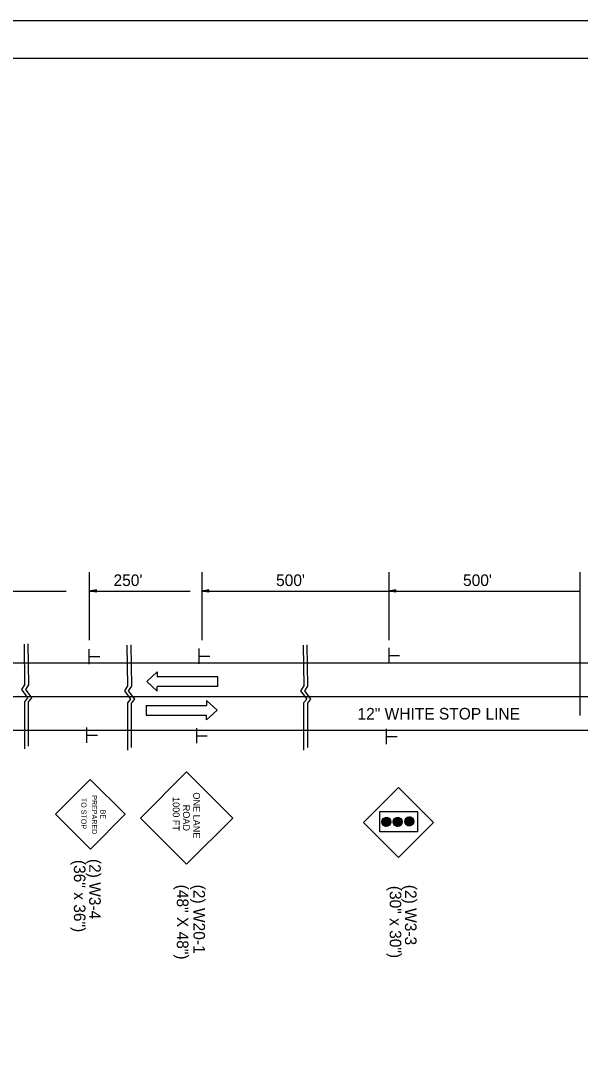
# Model space of a CAD drawing. Extents: x 1398460 to 1408037, y 380768 to 383968.
# Drawn here: x 1399523 to 1399812, y 382368 to 382901 of the extents above; entities that cross this region are included whole.
import ezdxf

# ---------------------------------------------------------------- set-up
doc = ezdxf.new("R2010")
doc.units = 0
for name, color, linetype in [('Default', 7, 'Continuous'), ('R_Border', 7, 'Continuous'), ('R_MOT', 7, 'Continuous'), ('R_No Plot', 7, 'Continuous')]:
    doc.layers.add(name, color=color, linetype=linetype)

msp = doc.modelspace()

# ---------------------------------------------------------------- linework, layer by layer
at = {"layer": 'Default'}
for p, q in [((1399558.31, 382615.8), (1399558.31, 382580.59)), ((1399616.41, 382615.8), (1399616.41, 382580.59)), ((1399713.06, 382615.8), (1399713.06, 382580.59)), ((1399811.91, 382615.8), (1399811.91, 382541.66)), ((1399494.15, 382606.01), (1399546.34, 382606.01)), ((1399562.06, 382606.57), (1399558.31, 382606.01)), ((1399558.31, 382606.01), (1399610.5, 382606.01)), ((1399562.06, 382605.45), (1399558.31, 382606.01)), ((1399562.06, 382606.48), (1399558.93, 382606.01)), ((1399562.06, 382605.54), (1399558.93, 382606.01)), ((1399562.06, 382606.39), (1399559.58, 382606.01)), ((1399562.06, 382605.64), (1399559.58, 382606.01)), ((1399562.06, 382606.29), (1399560.2, 382606.01)), ((1399562.06, 382605.73), (1399560.2, 382606.01)), ((1399562.06, 382606.2), (1399560.84, 382606.01)), ((1399562.06, 382605.83), (1399560.84, 382606.01)), ((1399562.06, 382606.1), (1399561.47, 382606.01)), ((1399562.06, 382605.92), (1399561.47, 382606.01)), ((1399562.06, 382605.45), (1399562.06, 382606.57)), ((1399620.16, 382606.57), (1399616.41, 382606.01)), ((1399616.41, 382606.01), (1399713.9, 382606.01)), ((1399620.16, 382605.45), (1399616.41, 382606.01)), ((1399620.16, 382606.48), (1399617.04, 382606.01)), ((1399620.16, 382605.54), (1399617.04, 382606.01)), ((1399620.16, 382606.39), (1399617.68, 382606.01)), ((1399620.16, 382605.64), (1399617.68, 382606.01)), ((1399620.16, 382606.29), (1399618.31, 382606.01)), ((1399620.16, 382605.73), (1399618.31, 382606.01)), ((1399620.16, 382606.2), (1399618.94, 382606.01)), ((1399620.16, 382605.83), (1399618.94, 382606.01)), ((1399620.16, 382606.1), (1399619.57, 382606.01)), ((1399620.16, 382605.92), (1399619.57, 382606.01)), ((1399620.16, 382605.45), (1399620.16, 382606.57)), ((1399716.81, 382606.57), (1399713.06, 382606.01)), ((1399713.06, 382606.01), (1399811.9, 382606.01)), ((1399716.81, 382605.45), (1399713.06, 382606.01)), ((1399716.81, 382606.48), (1399713.69, 382606.01)), ((1399716.81, 382605.54), (1399713.69, 382606.01)), ((1399716.81, 382606.39), (1399714.33, 382606.01)), ((1399716.81, 382605.64), (1399714.33, 382606.01)), ((1399716.81, 382606.29), (1399714.96, 382606.01)), ((1399716.81, 382605.73), (1399714.96, 382606.01)), ((1399716.81, 382606.2), (1399715.59, 382606.01)), ((1399716.81, 382605.83), (1399715.59, 382606.01)), ((1399716.81, 382606.1), (1399716.22, 382606.01)), ((1399716.81, 382605.92), (1399716.22, 382606.01)), ((1399716.81, 382605.45), (1399716.81, 382606.57)), ((1399558.31, 382568.22), (1399558.31, 382576.05)), ((1399615.11, 382568.43), (1399615.11, 382576.26)), ((1399713.25, 382568.85), (1399713.25, 382576.68)), ((1399518.14, 382568.89), (1399578.99, 382568.89)), ((1399558.42, 382572.11), (1399563.76, 382572.11)), ((1399578.99, 382568.89), (1399665.59, 382568.89)), ((1399615.23, 382572.32), (1399620.57, 382572.32)), ((1399665.59, 382568.89), (1399825.51, 382568.89)), ((1399713.36, 382572.75), (1399718.71, 382572.75)), ((1399517.8, 382551.51), (1399578.99, 382551.51)), ((1399578.99, 382551.51), (1399665.59, 382551.51)), ((1399665.59, 382551.51), (1399825.51, 382551.51)), ((1399517.46, 382534.12), (1399591.81, 382534.12)), ((1399557.04, 382527.58), (1399557.04, 382535.4)), ((1399557.16, 382531.47), (1399562.5, 382531.47)), ((1399578.99, 382534.12), (1399674.76, 382534.12)), ((1399613.85, 382527.37), (1399613.85, 382535.19)), ((1399613.96, 382531.26), (1399619.3, 382531.26)), ((1399665.59, 382534.12), (1399825.51, 382534.12)), ((1399711.99, 382526.94), (1399711.99, 382534.77)), ((1399712.1, 382530.84), (1399717.44, 382530.84)), ((1399584.72, 382488.66), (1399608.6, 382512.57)), ((1399632.51, 382488.66), (1399608.6, 382512.57)), ((1399540.77, 382490.6), (1399558.78, 382508.68)), ((1399576.84, 382490.66), (1399558.78, 382508.68)), ((1399700.12, 382486.35), (1399718.13, 382504.42)), ((1399736.19, 382486.41), (1399718.13, 382504.42)), ((1399558.85, 382472.59), (1399540.77, 382490.6)), ((1399558.85, 382472.59), (1399576.84, 382490.66)), ((1399608.6, 382464.76), (1399584.72, 382488.66)), ((1399608.6, 382464.76), (1399632.51, 382488.66)), ((1399709.67, 382487.68), (1399712.76, 382484.59)), ((1399709.72, 382487.78), (1399712.86, 382484.64)), ((1399709.77, 382487.87), (1399712.95, 382484.69)), ((1399709.83, 382487.96), (1399713.04, 382484.75)), ((1399709.88, 382488.05), (1399713.13, 382484.8)), ((1399709.94, 382488.13), (1399713.21, 382484.86)), ((1399710.01, 382488.21), (1399713.29, 382484.93)), ((1399710.07, 382488.29), (1399713.37, 382485)), ((1399710.15, 382488.36), (1399713.44, 382485.07)), ((1399710.22, 382488.43), (1399713.51, 382485.14)), ((1399710.29, 382488.5), (1399713.57, 382485.22)), ((1399710.37, 382488.56), (1399713.64, 382485.3)), ((1399710.46, 382488.62), (1399713.7, 382485.38)), ((1399710.54, 382488.68), (1399713.76, 382485.46)), ((1399710.63, 382488.73), (1399713.81, 382485.55)), ((1399710.73, 382488.78), (1399713.86, 382485.65)), ((1399710.82, 382488.83), (1399713.91, 382485.74)), ((1399710.92, 382488.87), (1399713.95, 382485.84)), ((1399711.03, 382488.91), (1399713.99, 382485.95)), ((1399711.14, 382488.94), (1399714.02, 382486.06)), ((1399711.25, 382488.97), (1399714.05, 382486.17)), ((1399711.37, 382489), (1399714.08, 382486.29)), ((1399711.49, 382489.02), (1399714.1, 382486.41)), ((1399711.62, 382489.03), (1399714.11, 382486.54)), ((1399711.76, 382489.04), (1399714.12, 382486.68)), ((1399711.9, 382489.03), (1399714.11, 382486.82)), ((1399712.06, 382489.02), (1399714.1, 382486.98)), ((1399712.23, 382489), (1399714.07, 382487.15)), ((1399712.42, 382488.95), (1399714.03, 382487.34)), ((1399712.63, 382488.88), (1399713.96, 382487.55)), ((1399712.9, 382488.75), (1399713.83, 382487.82)), ((1399715.58, 382487.73), (1399718.7, 382484.62)), ((1399715.63, 382487.82), (1399718.79, 382484.66)), ((1399715.68, 382487.91), (1399718.88, 382484.72)), ((1399715.74, 382488), (1399718.97, 382484.77)), ((1399715.8, 382488.09), (1399719.05, 382484.83)), ((1399715.86, 382488.17), (1399719.13, 382484.89)), ((1399715.93, 382488.24), (1399719.21, 382484.96)), ((1399715.99, 382488.32), (1399719.29, 382485.03)), ((1399716.07, 382488.39), (1399719.36, 382485.1)), ((1399716.14, 382488.46), (1399719.43, 382485.17)), ((1399716.22, 382488.52), (1399719.49, 382485.25)), ((1399716.3, 382488.59), (1399719.55, 382485.33)), ((1399716.38, 382488.65), (1399719.61, 382485.42)), ((1399716.47, 382488.7), (1399719.67, 382485.5)), ((1399716.56, 382488.75), (1399719.72, 382485.59)), ((1399716.66, 382488.8), (1399719.77, 382485.69)), ((1399716.75, 382488.85), (1399719.81, 382485.79)), ((1399716.86, 382488.89), (1399719.86, 382485.89)), ((1399716.96, 382488.93), (1399719.89, 382486)), ((1399717.07, 382488.96), (1399719.93, 382486.11)), ((1399717.19, 382488.99), (1399719.95, 382486.22)), ((1399717.31, 382489.01), (1399719.98, 382486.34)), ((1399717.44, 382489.02), (1399719.99, 382486.47)), ((1399717.57, 382489.03), (1399720, 382486.6)), ((1399717.71, 382489.04), (1399720, 382486.74)), ((1399717.86, 382489.03), (1399720, 382486.89)), ((1399718.02, 382489.01), (1399719.98, 382487.05)), ((1399718.2, 382488.98), (1399719.95, 382487.23)), ((1399718.4, 382488.92), (1399719.89, 382487.43)), ((1399718.63, 382488.83), (1399719.8, 382487.66)), ((1399718.94, 382488.66), (1399719.63, 382487.98)), ((1399721.56, 382487.74), (1399724.56, 382484.74)), ((1399721.6, 382487.84), (1399724.66, 382484.78)), ((1399721.65, 382487.94), (1399724.76, 382484.83)), ((1399721.69, 382488.04), (1399724.85, 382484.88)), ((1399721.75, 382488.13), (1399724.94, 382484.93)), ((1399721.8, 382488.21), (1399725.03, 382484.98)), ((1399721.86, 382488.3), (1399725.12, 382485.04)), ((1399721.92, 382488.38), (1399725.2, 382485.11)), ((1399721.99, 382488.46), (1399725.27, 382485.17)), ((1399722.06, 382488.53), (1399725.35, 382485.24)), ((1399722.13, 382488.6), (1399725.42, 382485.31)), ((1399722.2, 382488.67), (1399725.49, 382485.39)), ((1399722.28, 382488.74), (1399725.55, 382485.46)), ((1399722.36, 382488.8), (1399725.62, 382485.54)), ((1399722.45, 382488.86), (1399725.68, 382485.63)), ((1399722.53, 382488.91), (1399725.73, 382485.72)), ((1399722.62, 382488.97), (1399725.78, 382485.81)), ((1399722.72, 382489.02), (1399725.83, 382485.9)), ((1399722.82, 382489.06), (1399725.88, 382486)), ((1399722.92, 382489.1), (1399725.92, 382486.1)), ((1399723.03, 382489.14), (1399725.96, 382486.21)), ((1399723.14, 382489.17), (1399725.99, 382486.32)), ((1399723.25, 382489.2), (1399726.02, 382486.43)), ((1399723.37, 382489.22), (1399726.04, 382486.55)), ((1399723.5, 382489.24), (1399726.06, 382486.68)), ((1399723.63, 382489.25), (1399726.07, 382486.81)), ((1399723.77, 382489.25), (1399726.07, 382486.96)), ((1399723.92, 382489.24), (1399726.06, 382487.11)), ((1399724.09, 382489.22), (1399726.04, 382487.27)), ((1399724.26, 382489.19), (1399726.01, 382487.44)), ((1399724.46, 382489.14), (1399725.95, 382487.64)), ((1399724.69, 382489.05), (1399725.86, 382487.88)), ((1399725.01, 382488.88), (1399725.69, 382488.19)), ((1399718.19, 382468.34), (1399700.12, 382486.35)), ((1399709.46, 382486.75), (1399711.83, 382484.38)), ((1399709.46, 382486.61), (1399711.69, 382484.38)), ((1399709.47, 382486.89), (1399711.97, 382484.39)), ((1399709.47, 382486.45), (1399711.53, 382484.39)), ((1399709.48, 382487.02), (1399712.1, 382484.4)), ((1399709.5, 382487.14), (1399712.22, 382484.42)), ((1399709.5, 382486.29), (1399711.36, 382484.42)), ((1399709.53, 382487.26), (1399712.34, 382484.45)), ((1399709.54, 382486.1), (1399711.18, 382484.46)), ((1399709.56, 382487.37), (1399712.45, 382484.48)), ((1399709.59, 382487.48), (1399712.56, 382484.51)), ((1399709.61, 382485.89), (1399710.97, 382484.53)), ((1399709.72, 382485.63), (1399710.71, 382484.65)), ((1399710.03, 382485.18), (1399710.26, 382484.96)), ((1399715.35, 382486.81), (1399717.78, 382484.38)), ((1399715.35, 382486.67), (1399717.64, 382484.38)), ((1399715.36, 382486.95), (1399717.92, 382484.39)), ((1399715.36, 382486.52), (1399717.49, 382484.39)), ((1399715.37, 382486.36), (1399717.33, 382484.41)), ((1399715.38, 382487.07), (1399718.04, 382484.41)), ((1399715.4, 382487.2), (1399718.16, 382484.43)), ((1399715.41, 382486.18), (1399717.15, 382484.44)), ((1399715.43, 382487.31), (1399718.28, 382484.46)), ((1399715.46, 382487.42), (1399718.39, 382484.49)), ((1399715.46, 382485.99), (1399716.95, 382484.5)), ((1399715.5, 382487.53), (1399718.5, 382484.53)), ((1399715.54, 382487.63), (1399718.6, 382484.57)), ((1399715.55, 382485.75), (1399716.72, 382484.59)), ((1399715.73, 382485.44), (1399716.4, 382484.76)), ((1399718.19, 382468.34), (1399736.19, 382486.41)), ((1399721.41, 382487.03), (1399723.85, 382484.6)), ((1399721.41, 382486.89), (1399723.7, 382484.59)), ((1399721.42, 382487.16), (1399723.98, 382484.61)), ((1399721.42, 382486.74), (1399723.55, 382484.6)), ((1399721.44, 382487.29), (1399724.11, 382484.62)), ((1399721.44, 382486.58), (1399723.39, 382484.62)), ((1399721.46, 382487.41), (1399724.23, 382484.64)), ((1399721.47, 382486.4), (1399723.22, 382484.65)), ((1399721.49, 382487.52), (1399724.34, 382484.67)), ((1399721.52, 382487.63), (1399724.45, 382484.71)), ((1399721.53, 382486.2), (1399723.02, 382484.71)), ((1399721.62, 382485.97), (1399722.78, 382484.8)), ((1399721.79, 382485.65), (1399722.47, 382484.97))]:
    msp.add_line(p, q, dxfattribs=at)
for points in [[(1399524.56, 382578.6), (1399524.88, 382557.57), (1399523.26, 382555.15), (1399526.42, 382550.82), (1399524.76, 382548.82), (1399524.75, 382524.37)], [(1399526.56, 382578.79), (1399526.88, 382557.48), (1399525.26, 382555.07), (1399528.42, 382550.74), (1399526.76, 382548.74), (1399526.75, 382525.77)], [(1399577.79, 382577.97), (1399578.11, 382556.94), (1399576.48, 382554.52), (1399579.65, 382550.19), (1399577.98, 382548.19), (1399577.98, 382523.74)], [(1399579.78, 382578.16), (1399580.11, 382556.85), (1399578.48, 382554.44), (1399581.65, 382550.11), (1399579.98, 382548.11), (1399579.98, 382525.14)], [(1399668.83, 382577.97), (1399669.15, 382556.94), (1399667.53, 382554.52), (1399670.69, 382550.19), (1399669.03, 382548.19), (1399669.02, 382523.74)], [(1399670.83, 382578.16), (1399671.15, 382556.85), (1399669.53, 382554.44), (1399672.69, 382550.11), (1399671.03, 382548.11), (1399671.02, 382525.14)]]:
    msp.add_lwpolyline(points, dxfattribs=at)
msp.add_lwpolyline([(1399727.98, 382492.13), (1399727.98, 382481.6), (1399708.56, 382481.6), (1399708.56, 382492.13)], close=True, dxfattribs=at)
for centre in [(1399711.79, 382486.71), (1399717.68, 382486.71), (1399723.74, 382486.92)]:
    msp.add_circle(centre, 2.33, dxfattribs=at)
at = {"layer": 'R_Border'}
msp.add_line((1399060.87, 382881.42), (1400641.77, 382881.42), dxfattribs=at)
at = {"layer": 'R_MOT'}
for p, q in [((1399587.97, 382559.21), (1399593.46, 382564.21)), ((1399593.46, 382564.21), (1399593.46, 382561.71)), ((1399593.46, 382554.21), (1399587.97, 382559.21)), ((1399624.68, 382561.71), (1399593.46, 382561.71)), ((1399624.68, 382556.71), (1399624.68, 382561.71)), ((1399624.68, 382556.71), (1399593.46, 382556.71)), ((1399593.46, 382554.21), (1399593.46, 382556.71)), ((1399587.72, 382546.88), (1399618.94, 382546.88)), ((1399587.72, 382546.88), (1399587.72, 382541.88)), ((1399618.94, 382549.38), (1399624.42, 382544.38)), ((1399618.94, 382549.38), (1399618.94, 382546.88)), ((1399587.72, 382541.88), (1399618.94, 382541.88)), ((1399624.42, 382544.38), (1399618.94, 382539.38)), ((1399618.94, 382539.38), (1399618.94, 382541.88))]:
    msp.add_line(p, q, dxfattribs=at)
at = {"layer": 'R_No Plot'}
msp.add_line((1398998.86, 382900.89), (1400665.53, 382900.89), dxfattribs=at)
for points in [[(1398998.83, 382900.89), (1400665.53, 382900.89), (1400665.53, 381834.2), (1398998.83, 381834.2)], [(1400230.47, 382881.42), (1400328.57, 382881.42), (1400328.57, 382832.02), (1400409.13, 382832.02), (1400525.12, 382832.02), (1400525.12, 382710.36), (1400641.77, 382710.36), (1400641.77, 381854.12), (1399060.87, 381854.12), (1399060.87, 382881.42)]]:
    msp.add_lwpolyline(points, close=True, dxfattribs=at)

# ---------------------------------------------------------------- texts
at = {"layer": 'Default'}
for s, p in [("250'", (1399570.84, 382608.62)), ("500'", (1399654.85, 382608.62)), ("500'", (1399751.5, 382608.62)), ('12" WHITE STOP LINE', (1399696.95, 382539.61))]:
    msp.add_text(s, height=6, dxfattribs=at).set_placement(p)
for s, height, rotation, p in [('TO STOP', 2.675, 270.0006, (1399554.16, 382499.13)), ('PREPARED', 2.658, 270.1003, (1399559.63, 382500.48)), ('1000 FT', 3.522, 270.0006, (1399601.45, 382499.52)), ('ONE LANE', 3.521, 270.0004, (1399612.01, 382501.96)), ('ROAD', 3.52, 270, (1399606.73, 382495.57)), ('BE', 2.658, 270.1004, (1399564.08, 382493.02)), ('(36" x 36")', 6, 270, (1399550.34, 382467.02)), ('(2) W3-4', 6, 270, (1399558.24, 382467.55)), ('(48" X 48")', 6, 270, (1399603.56, 382454.24)), ('(2) W20-1', 6, 270, (1399612.12, 382454.24)), ('(30" x 30")', 6, 270, (1399713.58, 382453.63)), ('(2) W3-3', 6, 270, (1399721.48, 382454.16))]:
    msp.add_text(s, height=height, rotation=rotation, dxfattribs=at).set_placement(p)

doc.saveas('drawing.dxf')
